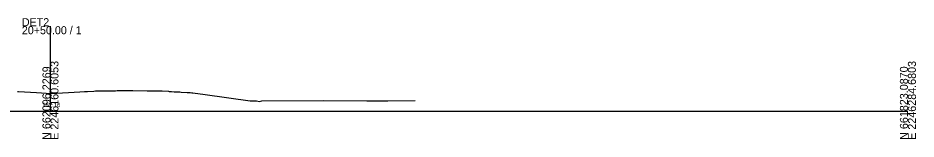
# Model space of a CAD drawing. Extents: x -26 to 603, y -10 to 9526.
# Drawn here: x 288.6 to 602.8, y 3490.3 to 3532.4 of the extents above; entities that cross this region are included whole.
import ezdxf

# ---------------------------------------------------------------- set-up
doc = ezdxf.new("R2010")
doc.units = 0
for name, color, linetype in [('Exist Cross Section Cell', 7, 'Continuous'), ('Exist XS Center Line Elevation Label', 7, 'Continuous'), ('Exist XS Ground Line', 7, 'Continuous')]:
    doc.layers.add(name, color=color, linetype=linetype)

msp = doc.modelspace()

# ---------------------------------------------------------------- linework, layer by layer
at = {"layer": 'Exist Cross Section Cell'}
for p, q in [((300, 3500), (300, 3529.59)), ((0, 3500), (300, 3500)), ((300, 3500), (600, 3500))]:
    msp.add_line(p, q, dxfattribs=at)
at = {"layer": 'Exist XS Ground Line'}
for p, q in [((288.48, 3506.86), (288.79, 3506.84)), ((288.79, 3506.84), (295.09, 3506.5)), ((300.25, 3506.14), (310.23, 3506.73)), ((310.23, 3506.73), (311.9, 3506.83)), ((311.9, 3506.83), (312.22, 3506.85)), ((312.22, 3506.85), (312.93, 3506.89)), ((312.93, 3506.89), (315.19, 3507)), ((315.19, 3507), (315.71, 3507.03)), ((315.71, 3507.03), (316.87, 3507.05)), ((316.87, 3507.05), (317.22, 3507.05)), ((317.22, 3507.05), (317.82, 3507.05)), ((317.82, 3507.05), (319.35, 3507.08)), ((319.35, 3507.08), (322.72, 3507.13)), ((322.72, 3507.13), (323.31, 3507.14)), ((323.31, 3507.14), (325.44, 3507.17)), ((325.44, 3507.17), (326.29, 3507.18)), ((326.29, 3507.18), (327.09, 3507.19)), ((327.09, 3507.19), (327.68, 3507.2)), ((327.68, 3507.2), (328.81, 3507.18)), ((328.81, 3507.18), (333.88, 3507.1)), ((333.88, 3507.1), (334.3, 3507.09)), ((334.3, 3507.09), (334.8, 3507.08)), ((334.8, 3507.08), (339.12, 3507.02)), ((339.12, 3507.02), (341.29, 3506.94)), ((341.29, 3506.94), (341.48, 3506.88)), ((341.48, 3506.88), (342.37, 3506.82)), ((342.37, 3506.82), (343.34, 3506.75)), ((343.34, 3506.75), (345.28, 3506.67)), ((345.28, 3506.67), (345.78, 3506.64)), ((345.78, 3506.64), (347.82, 3506.54)), ((347.82, 3506.54), (348.53, 3506.49)), ((295.09, 3506.5), (300.25, 3506.14)), ((348.53, 3506.49), (348.91, 3506.47)), ((348.91, 3506.47), (349.44, 3506.43)), ((349.44, 3506.43), (349.87, 3506.43)), ((349.87, 3506.43), (354.09, 3505.84)), ((354.09, 3505.84), (369.86, 3503.58)), ((369.86, 3503.58), (372.06, 3503.59)), ((372.06, 3503.59), (373.1, 3503.32)), ((373.1, 3503.32), (373.94, 3503.6)), ((373.94, 3503.6), (395.6, 3503.73)), ((395.6, 3503.73), (410.67, 3503.64)), ((410.67, 3503.64), (418, 3503.59)), ((418, 3503.59), (427.65, 3503.67))]:
    msp.add_line(p, q, dxfattribs=at)

# ---------------------------------------------------------------- texts
at = {"layer": 'Exist Cross Section Cell'}
for s, p in [('DET2', (290, 3529.59)), ('20+50.00 / 1', (290, 3526.79))]:
    msp.add_text(s, height=2.8, dxfattribs=at).set_placement(p)
for s, p in [('E 2246160.6053', (302.8, 3490)), ('E 2246284.6803', (602.8, 3490)), ('N 662096.2269', (300, 3490)), ('N 661823.0870', (600, 3490))]:
    msp.add_text(s, height=2.8, rotation=90, dxfattribs=at).set_placement(p)
at = {"layer": 'Exist XS Center Line Elevation Label'}
msp.add_text('152.16', height=1.5, dxfattribs=at).set_placement((297.16, 3501.41))

doc.saveas('drawing.dxf')
